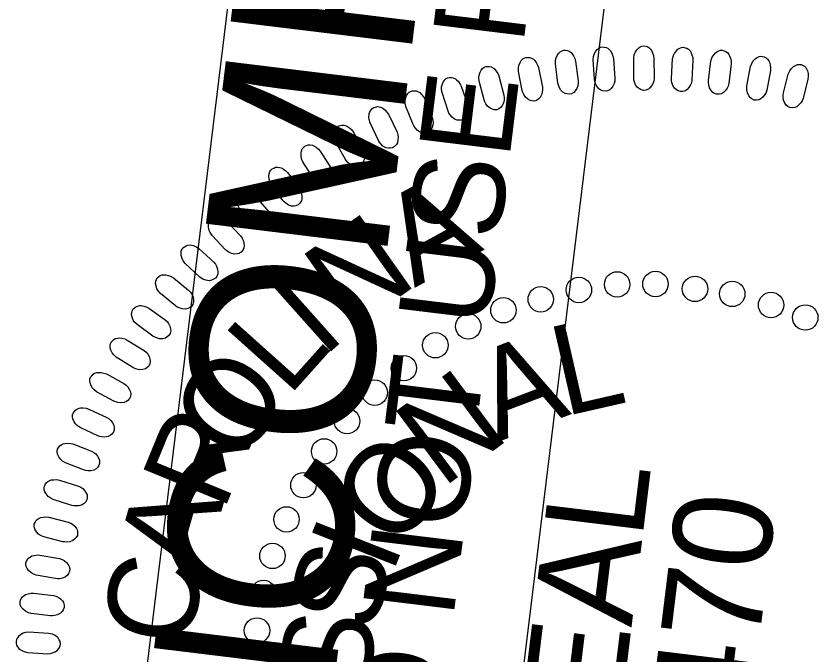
# Model space of a CAD drawing. Extents: x 480344 to 482186, y 489602 to 491961.
# Drawn here: x 481070.6 to 481121.1, y 491781.5 to 491821.7 of the extents above; entities that cross this region are included whole.
import ezdxf

# ---------------------------------------------------------------- set-up
doc = ezdxf.new("R2010")
doc.units = 0
doc.layers.add('Sheet PE Seal Cell', color=7, linetype='Continuous')
doc.layers.add('Sheet Sticker Incomplete CELL', color=7, linetype='Continuous')

msp = doc.modelspace()

# ---------------------------------------------------------------- linework, layer by layer
at = {"layer": 'Sheet PE Seal Cell'}
for points in [[(481109.499, 491817.8), (481109.495, 491819.027), (481109.531, 491819.246), (481109.582, 491819.387), (481109.694, 491819.557), (481109.79, 491819.667), (481109.902, 491819.747), (481110.007, 491819.787), (481110.119, 491819.807), (481110.231, 491819.788), (481110.351, 491819.758), (481110.456, 491819.699), (481110.561, 491819.6), (481110.62, 491819.52), (481110.689, 491819.371), (481110.749, 491819.191), (481110.773, 491819.032), (481110.785, 491817.775), (481110.762, 491817.606), (481110.718, 491817.466), (481110.629, 491817.306), (481110.518, 491817.166), (481110.421, 491817.086), (481110.264, 491817.025), (481110.114, 491817.005), (481109.965, 491817.044), (481109.86, 491817.094), (481109.733, 491817.193), (481109.612, 491817.362), (481109.545, 491817.541), (481109.514, 491817.671)], [(481104.73, 491817.468), (481104.572, 491818.685), (481104.58, 491818.906), (481104.614, 491819.052), (481104.703, 491819.235), (481104.785, 491819.357), (481104.886, 491819.45), (481104.985, 491819.503), (481105.094, 491819.537), (481105.207, 491819.532), (481105.33, 491819.517), (481105.441, 491819.472), (481105.558, 491819.387), (481105.628, 491819.315), (481105.713, 491819.175), (481105.796, 491819.005), (481105.839, 491818.85), (481106.008, 491817.605), (481106.008, 491817.434), (481105.982, 491817.289), (481105.913, 491817.12), (481105.821, 491816.967), (481105.734, 491816.875), (481105.586, 491816.795), (481105.441, 491816.756), (481105.287, 491816.777), (481105.177, 491816.813), (481105.038, 491816.895), (481104.898, 491817.047), (481104.808, 491817.217), (481104.762, 491817.342)], [(481107.029, 491817.701), (481106.948, 491818.925), (481106.971, 491819.146), (481107.013, 491819.289), (481107.114, 491819.466), (481107.203, 491819.581), (481107.31, 491819.669), (481107.411, 491819.715), (481107.522, 491819.743), (481107.635, 491819.73), (481107.757, 491819.708), (481107.865, 491819.656), (481107.976, 491819.563), (481108.041, 491819.488), (481108.118, 491819.343), (481108.19, 491819.168), (481108.223, 491819.01), (481108.314, 491817.756), (481108.303, 491817.586), (481108.267, 491817.444), (481108.188, 491817.279), (481108.086, 491817.132), (481107.995, 491817.046), (481107.841, 491816.975), (481107.693, 491816.946), (481107.542, 491816.976), (481107.434, 491817.018), (481107.301, 491817.109), (481107.171, 491817.271), (481107.091, 491817.446), (481107.053, 491817.573)], [(481111.875, 491817.756), (481111.948, 491818.98), (481111.999, 491819.196), (481112.058, 491819.333), (481112.181, 491819.496), (481112.284, 491819.599), (481112.401, 491819.672), (481112.507, 491819.706), (481112.621, 491819.719), (481112.731, 491819.693), (481112.849, 491819.656), (481112.95, 491819.59), (481113.049, 491819.484), (481113.103, 491819.401), (481113.162, 491819.248), (481113.211, 491819.065), (481113.224, 491818.905), (481113.157, 491817.649), (481113.125, 491817.482), (481113.071, 491817.345), (481112.973, 491817.191), (481112.853, 491817.058), (481112.751, 491816.984), (481112.591, 491816.934), (481112.44, 491816.923), (481112.294, 491816.971), (481112.192, 491817.028), (481112.071, 491817.135), (481111.962, 491817.31), (481111.905, 491817.494), (481111.883, 491817.625)], [(481114.207, 491817.621), (481114.356, 491818.839), (481114.42, 491819.052), (481114.489, 491819.184), (481114.621, 491819.339), (481114.73, 491819.436), (481114.851, 491819.501), (481114.96, 491819.528), (481115.074, 491819.534), (481115.183, 491819.501), (481115.298, 491819.457), (481115.394, 491819.385), (481115.486, 491819.273), (481115.536, 491819.186), (481115.584, 491819.029), (481115.622, 491818.844), (481115.625, 491818.684), (481115.48, 491817.435), (481115.437, 491817.27), (481115.374, 491817.136), (481115.266, 491816.989), (481115.139, 491816.864), (481115.032, 491816.796), (481114.869, 491816.756), (481114.718, 491816.755), (481114.575, 491816.813), (481114.477, 491816.875), (481114.363, 491816.989), (481114.265, 491817.172), (481114.22, 491817.358), (481114.206, 491817.491)], [(481102.482, 491816.992), (481102.248, 491818.197), (481102.243, 491818.419), (481102.267, 491818.567), (481102.345, 491818.754), (481102.419, 491818.881), (481102.514, 491818.98), (481102.609, 491819.039), (481102.716, 491819.08), (481102.829, 491819.082), (481102.953, 491819.076), (481103.066, 491819.037), (481103.189, 491818.959), (481103.263, 491818.892), (481103.358, 491818.758), (481103.45, 491818.594), (481103.503, 491818.441), (481103.751, 491817.209), (481103.76, 491817.039), (481103.743, 491816.893), (481103.686, 491816.719), (481103.603, 491816.561), (481103.522, 491816.463), (481103.38, 491816.374), (481103.237, 491816.327), (481103.082, 491816.337), (481102.97, 491816.366), (481102.826, 491816.44), (481102.677, 491816.583), (481102.576, 491816.747), (481102.522, 491816.868)], [(481116.626, 491817.292), (481116.85, 491818.498), (481116.928, 491818.706), (481117.004, 491818.834), (481117.146, 491818.981), (481117.262, 491819.071), (481117.386, 491819.128), (481117.496, 491819.148), (481117.611, 491819.147), (481117.717, 491819.107), (481117.829, 491819.056), (481117.921, 491818.978), (481118.005, 491818.861), (481118.05, 491818.771), (481118.088, 491818.611), (481118.114, 491818.424), (481118.107, 491818.263), (481117.884, 491817.027), (481117.83, 491816.864), (481117.76, 491816.735), (481117.643, 491816.595), (481117.507, 491816.479), (481117.397, 491816.417), (481117.232, 491816.387), (481117.081, 491816.396), (481116.942, 491816.462), (481116.848, 491816.53), (481116.741, 491816.652), (481116.655, 491816.84), (481116.622, 491817.03), (481116.616, 491817.162)], [(481100.079, 491816.405), (481099.77, 491817.593), (481099.751, 491817.814), (481099.766, 491817.962), (481099.831, 491818.155), (481099.898, 491818.285), (481099.986, 491818.391), (481100.078, 491818.456), (481100.181, 491818.504), (481100.295, 491818.512), (481100.418, 491818.514), (481100.534, 491818.482), (481100.661, 491818.412), (481100.739, 491818.35), (481100.842, 491818.222), (481100.945, 491818.064), (481101.006, 491817.915), (481101.331, 491816.701), (481101.352, 491816.531), (481101.344, 491816.385), (481101.297, 491816.208), (481101.224, 491816.045), (481101.15, 491815.942), (481101.013, 491815.845), (481100.873, 491815.788), (481100.719, 491815.789), (481100.605, 491815.811), (481100.457, 491815.875), (481100.299, 491816.009), (481100.188, 491816.166), (481100.127, 491816.284)], [(481118.928, 491816.843), (481119.228, 491818.033), (481119.318, 491818.236), (481119.403, 491818.359), (481119.553, 491818.497), (481119.675, 491818.579), (481119.803, 491818.628), (481119.914, 491818.641), (481120.028, 491818.633), (481120.131, 491818.586), (481120.24, 491818.528), (481120.327, 491818.444), (481120.404, 491818.322), (481120.442, 491818.23), (481120.471, 491818.068), (481120.485, 491817.88), (481120.467, 491817.72), (481120.167, 491816.499), (481120.104, 491816.34), (481120.026, 491816.216), (481119.9, 491816.084), (481119.757, 491815.976), (481119.643, 491815.922), (481119.476, 491815.903), (481119.327, 491815.92), (481119.191, 491815.995), (481119.102, 491816.069), (481119.003, 491816.197), (481118.929, 491816.39), (481118.907, 491816.581), (481118.911, 491816.714)], [(481097.815, 491815.695), (481097.432, 491816.86), (481097.399, 491817.08), (481097.404, 491817.229), (481097.458, 491817.426), (481097.517, 491817.56), (481097.598, 491817.671), (481097.685, 491817.742), (481097.785, 491817.796), (481097.898, 491817.812), (481098.021, 491817.82), (481098.139, 491817.797), (481098.27, 491817.734), (481098.351, 491817.678), (481098.462, 491817.556), (481098.575, 491817.404), (481098.646, 491817.26), (481099.046, 491816.068), (481099.077, 491815.901), (481099.079, 491815.754), (481099.043, 491815.575), (481098.98, 491815.407), (481098.913, 491815.3), (481098.782, 491815.194), (481098.647, 491815.129), (481098.493, 491815.12), (481098.377, 491815.135), (481098.225, 491815.189), (481098.059, 491815.314), (481097.939, 491815.463), (481097.87, 491815.577)], [(481095.614, 491814.848), (481095.158, 491815.987), (481095.111, 491816.205), (481095.107, 491816.354), (481095.148, 491816.553), (481095.198, 491816.691), (481095.273, 491816.807), (481095.355, 491816.882), (481095.451, 491816.943), (481095.563, 491816.966), (481095.685, 491816.982), (481095.804, 491816.966), (481095.939, 491816.913), (481096.024, 491816.861), (481096.142, 491816.747), (481096.264, 491816.602), (481096.344, 491816.462), (481096.818, 491815.299), (481096.86, 491815.133), (481096.87, 491814.986), (481096.846, 491814.805), (481096.794, 491814.634), (481096.734, 491814.523), (481096.61, 491814.41), (481096.479, 491814.336), (481096.326, 491814.317), (481096.21, 491814.324), (481096.054, 491814.37), (481095.881, 491814.483), (481095.751, 491814.625), (481095.675, 491814.734)], [(481093.426, 491813.845), (481092.899, 491814.953), (481092.839, 491815.168), (481092.826, 491815.316), (481092.854, 491815.517), (481092.895, 491815.658), (481092.962, 491815.778), (481093.04, 491815.859), (481093.132, 491815.925), (481093.242, 491815.956), (481093.363, 491815.98), (481093.483, 491815.971), (481093.621, 491815.925), (481093.709, 491815.879), (481093.834, 491815.772), (481093.965, 491815.636), (481094.054, 491815.502), (481094.6, 491814.371), (481094.652, 491814.208), (481094.671, 491814.062), (481094.659, 491813.88), (481094.618, 491813.705), (481094.564, 491813.591), (481094.448, 491813.47), (481094.322, 491813.388), (481094.17, 491813.36), (481094.054, 491813.36), (481093.896, 491813.395), (481093.715, 491813.497), (481093.577, 491813.631), (481093.495, 491813.735)], [(481091.324, 491812.691), (481090.73, 491813.764), (481090.656, 491813.974), (481090.633, 491814.121), (481090.649, 491814.324), (481090.681, 491814.467), (481090.74, 491814.591), (481090.813, 491814.677), (481090.901, 491814.749), (481091.009, 491814.786), (481091.128, 491814.817), (481091.248, 491814.816), (481091.388, 491814.779), (481091.479, 491814.739), (481091.611, 491814.64), (481091.75, 491814.512), (481091.847, 491814.384), (481092.463, 491813.289), (481092.525, 491813.13), (481092.554, 491812.985), (481092.553, 491812.803), (481092.523, 491812.626), (481092.477, 491812.509), (481092.368, 491812.381), (481092.247, 491812.29), (481092.097, 491812.253), (481091.982, 491812.246), (481091.822, 491812.271), (481091.635, 491812.362), (481091.489, 491812.486), (481091.4, 491812.585)], [(481089.338, 491811.462), (481088.677, 491812.496), (481088.59, 491812.701), (481088.559, 491812.847), (481088.562, 491813.05), (481088.585, 491813.195), (481088.636, 491813.322), (481088.703, 491813.412), (481088.787, 491813.49), (481088.892, 491813.533), (481089.009, 491813.572), (481089.129, 491813.579), (481089.271, 491813.551), (481089.365, 491813.516), (481089.502, 491813.426), (481089.648, 491813.307), (481089.754, 491813.185), (481090.437, 491812.13), (481090.51, 491811.976), (481090.547, 491811.834), (481090.557, 491811.651), (481090.539, 491811.473), (481090.5, 491811.353), (481090.4, 491811.218), (481090.284, 491811.121), (481090.137, 491811.074), (481090.022, 491811.059), (481089.861, 491811.075), (481089.669, 491811.153), (481089.516, 491811.268), (481089.421, 491811.361)], [(481087.409, 491810.074), (481086.685, 491811.064), (481086.586, 491811.263), (481086.545, 491811.407), (481086.535, 491811.609), (481086.549, 491811.755), (481086.592, 491811.886), (481086.653, 491811.98), (481086.731, 491812.063), (481086.834, 491812.112), (481086.948, 491812.159), (481087.068, 491812.173), (481087.211, 491812.154), (481087.306, 491812.125), (481087.449, 491812.044), (481087.603, 491811.935), (481087.716, 491811.819), (481088.464, 491810.809), (481088.546, 491810.66), (481088.593, 491810.52), (481088.614, 491810.339), (481088.607, 491810.16), (481088.575, 491810.038), (481088.484, 491809.897), (481088.375, 491809.792), (481088.231, 491809.736), (481088.117, 491809.715), (481087.956, 491809.72), (481087.759, 491809.786), (481087.599, 491809.892), (481087.498, 491809.979)], [(481085.517, 491808.548), (481084.732, 491809.49), (481084.619, 491809.682), (481084.57, 491809.823), (481084.548, 491810.025), (481084.552, 491810.172), (481084.587, 491810.305), (481084.642, 491810.403), (481084.716, 491810.49), (481084.814, 491810.546), (481084.925, 491810.6), (481085.044, 491810.621), (481085.188, 491810.611), (481085.286, 491810.588), (481085.433, 491810.516), (481085.594, 491810.417), (481085.713, 491810.309), (481086.523, 491809.348), (481086.615, 491809.204), (481086.67, 491809.068), (481086.703, 491808.888), (481086.707, 491808.709), (481086.683, 491808.585), (481086.601, 491808.438), (481086.498, 491808.327), (481086.358, 491808.263), (481086.246, 491808.234), (481086.085, 491808.229), (481085.884, 491808.283), (481085.718, 491808.377), (481085.612, 491808.458)], [(481083.8, 491806.973), (481082.956, 491807.864), (481082.833, 491808.049), (481082.775, 491808.186), (481082.739, 491808.387), (481082.734, 491808.533), (481082.761, 491808.668), (481082.81, 491808.769), (481082.878, 491808.861), (481082.972, 491808.923), (481083.08, 491808.983), (481083.197, 491809.012), (481083.342, 491809.011), (481083.44, 491808.995), (481083.592, 491808.932), (481083.759, 491808.843), (481083.885, 491808.743), (481084.754, 491807.835), (481084.854, 491807.696), (481084.917, 491807.564), (481084.962, 491807.387), (481084.977, 491807.208), (481084.961, 491807.083), (481084.888, 491806.932), (481084.793, 491806.815), (481084.657, 491806.741), (481084.547, 491806.705), (481084.386, 491806.69), (481084.183, 491806.731), (481084.01, 491806.816), (481083.899, 491806.889)], [(481082.164, 491805.264), (481081.267, 491806.1), (481081.131, 491806.277), (481081.065, 491806.411), (481081.017, 491806.608), (481081.003, 491806.754), (481081.021, 491806.89), (481081.064, 491806.995), (481081.125, 491807.09), (481081.216, 491807.159), (481081.32, 491807.225), (481081.435, 491807.261), (481081.579, 491807.27), (481081.679, 491807.26), (481081.834, 491807.207), (481082.006, 491807.128), (481082.138, 491807.036), (481083.062, 491806.184), (481083.171, 491806.052), (481083.242, 491805.924), (481083.298, 491805.75), (481083.324, 491805.573), (481083.316, 491805.447), (481083.253, 491805.291), (481083.165, 491805.169), (481083.034, 491805.086), (481082.926, 491805.044), (481082.767, 491805.019), (481082.561, 491805.047), (481082.384, 491805.12), (481082.269, 491805.187)], [(481080.658, 491803.434), (481079.71, 491804.212), (481079.564, 491804.38), (481079.489, 491804.509), (481079.429, 491804.703), (481079.405, 491804.848), (481079.415, 491804.985), (481079.451, 491805.091), (481079.507, 491805.191), (481079.593, 491805.265), (481079.692, 491805.337), (481079.805, 491805.381), (481079.948, 491805.399), (481080.048, 491805.394), (481080.207, 491805.351), (481080.383, 491805.284), (481080.521, 491805.2), (481081.497, 491804.408), (481081.613, 491804.283), (481081.693, 491804.16), (481081.759, 491803.989), (481081.796, 491803.814), (481081.797, 491803.688), (481081.743, 491803.529), (481081.663, 491803.401), (481081.538, 491803.311), (481081.432, 491803.262), (481081.275, 491803.226), (481081.068, 491803.242), (481080.887, 491803.303), (481080.767, 491803.363)], [(481079.232, 491801.534), (481078.237, 491802.251), (481078.081, 491802.41), (481077.998, 491802.534), (481077.926, 491802.724), (481077.894, 491802.867), (481077.895, 491803.005), (481077.923, 491803.113), (481077.973, 491803.216), (481078.055, 491803.295), (481078.149, 491803.374), (481078.258, 491803.424), (481078.401, 491803.451), (481078.5, 491803.453), (481078.661, 491803.42), (481078.842, 491803.363), (481078.984, 491803.289), (481080.008, 491802.56), (481080.132, 491802.442), (481080.22, 491802.324), (481080.297, 491802.159), (481080.344, 491801.985), (481080.352, 491801.86), (481080.309, 491801.698), (481080.238, 491801.565), (481080.118, 491801.466), (481080.016, 491801.411), (481079.861, 491801.366), (481079.653, 491801.368), (481079.469, 491801.419), (481079.345, 491801.47)], [(481077.967, 491799.549), (481076.928, 491800.202), (481076.763, 491800.351), (481076.672, 491800.469), (481076.588, 491800.655), (481076.547, 491800.795), (481076.54, 491800.933), (481076.562, 491801.042), (481076.605, 491801.148), (481076.681, 491801.232), (481076.77, 491801.318), (481076.876, 491801.374), (481077.017, 491801.41), (481077.116, 491801.418), (481077.279, 491801.395), (481077.462, 491801.35), (481077.61, 491801.284), (481078.677, 491800.621), (481078.808, 491800.512), (481078.903, 491800.399), (481078.99, 491800.238), (481079.048, 491800.069), (481079.064, 491799.944), (481079.031, 491799.779), (481078.968, 491799.642), (481078.855, 491799.538), (481078.757, 491799.476), (481078.605, 491799.421), (481078.398, 491799.41), (481078.21, 491799.449), (481078.085, 491799.493)], [(481076.768, 491797.437), (481075.691, 491798.024), (481075.516, 491798.162), (481075.418, 491798.274), (481075.323, 491798.454), (481075.273, 491798.592), (481075.257, 491798.729), (481075.272, 491798.84), (481075.307, 491798.948), (481075.379, 491799.036), (481075.462, 491799.127), (481075.565, 491799.19), (481075.703, 491799.235), (481075.801, 491799.249), (481075.965, 491799.237), (481076.151, 491799.204), (481076.302, 491799.147), (481077.409, 491798.552), (481077.547, 491798.451), (481077.648, 491798.345), (481077.745, 491798.19), (481077.815, 491798.025), (481077.838, 491797.901), (481077.815, 491797.735), (481077.761, 491797.594), (481077.655, 491797.482), (481077.561, 491797.414), (481077.413, 491797.35), (481077.206, 491797.326), (481077.017, 491797.352), (481076.889, 491797.389)], [(481075.761, 491795.26), (481074.649, 491795.778), (481074.466, 491795.905), (481074.362, 491796.011), (481074.255, 491796.184), (481074.197, 491796.319), (481074.172, 491796.454), (481074.18, 491796.566), (481074.209, 491796.676), (481074.275, 491796.769), (481074.353, 491796.865), (481074.451, 491796.935), (481074.585, 491796.987), (481074.683, 491797.007), (481074.847, 491797.006), (481075.035, 491796.984), (481075.189, 491796.937), (481076.331, 491796.413), (481076.476, 491796.321), (481076.583, 491796.221), (481076.691, 491796.073), (481076.769, 491795.912), (481076.801, 491795.79), (481076.789, 491795.622), (481076.743, 491795.478), (481076.644, 491795.36), (481076.555, 491795.286), (481076.411, 491795.213), (481076.207, 491795.176), (481076.015, 491795.191), (481075.885, 491795.219)], [(481074.871, 491793.102), (481073.729, 491793.549), (481073.539, 491793.664), (481073.427, 491793.764), (481073.31, 491793.93), (481073.243, 491794.06), (481073.21, 491794.194), (481073.211, 491794.306), (481073.233, 491794.418), (481073.293, 491794.515), (481073.364, 491794.615), (481073.458, 491794.691), (481073.589, 491794.752), (481073.685, 491794.778), (481073.849, 491794.786), (481074.038, 491794.777), (481074.195, 491794.74), (481075.368, 491794.288), (481075.517, 491794.205), (481075.631, 491794.112), (481075.747, 491793.971), (481075.836, 491793.816), (481075.875, 491793.696), (481075.873, 491793.528), (481075.837, 491793.382), (481075.745, 491793.257), (481075.661, 491793.178), (481075.522, 491793.096), (481075.32, 491793.046), (481075.129, 491793.049), (481074.998, 491793.069)], [(481074.121, 491790.871), (481072.953, 491791.246), (481072.756, 491791.348), (481072.639, 491791.441), (481072.512, 491791.6), (481072.437, 491791.725), (481072.395, 491791.856), (481072.389, 491791.968), (481072.404, 491792.082), (481072.457, 491792.182), (481072.523, 491792.287), (481072.612, 491792.368), (481072.739, 491792.437), (481072.832, 491792.47), (481072.996, 491792.488), (481073.185, 491792.491), (481073.344, 491792.463), (481074.543, 491792.086), (481074.697, 491792.013), (481074.816, 491791.928), (481074.941, 491791.794), (481075.04, 491791.644), (481075.086, 491791.527), (481075.095, 491791.36), (481075.068, 491791.211), (481074.985, 491791.081), (481074.905, 491790.997), (481074.772, 491790.906), (481074.574, 491790.844), (481074.382, 491790.835), (481074.249, 491790.846)], [(481073.553, 491788.584), (481072.364, 491788.885), (481072.16, 491788.974), (481072.038, 491789.059), (481071.901, 491789.209), (481071.818, 491789.331), (481071.769, 491789.459), (481071.755, 491789.57), (481071.764, 491789.684), (481071.811, 491789.788), (481071.869, 491789.896), (481071.953, 491789.983), (481072.075, 491790.06), (481072.167, 491790.098), (481072.329, 491790.127), (481072.517, 491790.141), (481072.677, 491790.124), (481073.898, 491789.823), (481074.056, 491789.759), (481074.18, 491789.682), (481074.313, 491789.556), (481074.421, 491789.413), (481074.475, 491789.3), (481074.494, 491789.132), (481074.477, 491788.983), (481074.402, 491788.847), (481074.328, 491788.758), (481074.2, 491788.659), (481074.006, 491788.585), (481073.816, 491788.564), (481073.682, 491788.567)], [(481073.093, 491786.26), (481071.887, 491786.485), (481071.678, 491786.562), (481071.551, 491786.639), (481071.405, 491786.781), (481071.315, 491786.896), (481071.257, 491787.021), (481071.237, 491787.132), (481071.238, 491787.246), (481071.279, 491787.352), (481071.33, 491787.464), (481071.408, 491787.556), (481071.525, 491787.641), (481071.614, 491787.684), (481071.774, 491787.724), (481071.961, 491787.749), (481072.122, 491787.742), (481073.359, 491787.518), (481073.521, 491787.465), (481073.65, 491787.395), (481073.79, 491787.278), (481073.907, 491787.142), (481073.968, 491787.032), (481073.998, 491786.867), (481073.99, 491786.716), (481073.924, 491786.576), (481073.855, 491786.483), (481073.733, 491786.376), (481073.545, 491786.29), (481073.356, 491786.256), (481073.223, 491786.251)], [(481072.781, 491783.921), (481071.563, 491784.07), (481071.35, 491784.134), (481071.217, 491784.204), (481071.063, 491784.335), (481070.966, 491784.445), (481070.9, 491784.566), (481070.874, 491784.675), (481070.867, 491784.789), (481070.901, 491784.897), (481070.945, 491785.013), (481071.017, 491785.109), (481071.129, 491785.201), (481071.216, 491785.25), (481071.372, 491785.299), (481071.558, 491785.337), (481071.719, 491785.34), (481072.967, 491785.194), (481073.132, 491785.152), (481073.265, 491785.09), (481073.413, 491784.981), (481073.538, 491784.853), (481073.605, 491784.747), (481073.645, 491784.583), (481073.647, 491784.433), (481073.59, 491784.29), (481073.527, 491784.192), (481073.413, 491784.077), (481073.23, 491783.979), (481073.044, 491783.934), (481072.911, 491783.921)], [(481072.655, 491782.813), (481071.43, 491782.886), (481071.209, 491782.861), (481071.067, 491782.817), (481070.89, 491782.715), (481070.775, 491782.625), (481070.689, 491782.518), (481070.643, 491782.416), (481070.617, 491782.304), (481070.63, 491782.192), (481070.652, 491782.071), (481070.706, 491781.962), (481070.8, 491781.852), (481070.876, 491781.788), (481071.021, 491781.712), (481071.197, 491781.641), (481071.354, 491781.61), (481072.609, 491781.528), (481072.779, 491781.54), (481072.921, 491781.577), (481073.086, 491781.657), (481073.232, 491781.761), (481073.317, 491781.853), (481073.386, 491782.007), (481073.415, 491782.154), (481073.384, 491782.306), (481073.34, 491782.414), (481073.248, 491782.546), (481073.086, 491782.676), (481072.91, 491782.753), (481072.783, 491782.791)]]:
    msp.add_lwpolyline(points, close=True, dxfattribs=at)
for centre in [(481106.045, 491804.437), (481108.455, 491804.784), (481110.866, 491804.81), (481113.357, 491804.504), (481103.645, 491803.849), (481115.7, 491804.188), (481118.143, 491803.488), (481101.294, 491803.157), (481120.294, 491802.703), (481099.083, 491802.144), (481097.011, 491800.954), (481095.028, 491799.512), (481093.194, 491797.971), (481091.45, 491796.18), (481090.012, 491794.27), (481088.708, 491792.143), (481087.641, 491789.988), (481086.757, 491787.689), (481086.19, 491785.352), (481085.781, 491782.995)]:
    msp.add_circle(centre, 0.801, dxfattribs=at)
at = {"layer": 'Sheet Sticker Incomplete CELL'}
msp.add_lwpolyline([(481099.711, 491757.426), (481076.384, 491760.275), (481094.206, 491906.191), (481117.533, 491903.342)], close=True, dxfattribs=at)

# ---------------------------------------------------------------- texts
at = {"layer": 'Sheet PE Seal Cell'}
for s, height, rotation, p in [('A', 5.669, 28.7093, (481095.698, 491804.558)), ('N', 5.669, 35.1987, (481091.544, 491801.721)), ('I', 5.669, 41.688, (481089.915, 491800.101)), ('L', 5.669, 48.1774, (481087.749, 491797.653)), ('L', 5.669, 12.8674, (481105.12, 491796.464)), ('A', 5.669, 20.8072, (481100.898, 491794.84)), ('O', 5.669, 54.6668, (481084.663, 491793.261)), ('N', 5.669, 36.6868, (481097.435, 491791.901)), ('R', 5.669, 67.6455, (481083.655, 491790.408)), ('O', 5.669, 52.5664, (481094.625, 491787.901)), ('SEAL', 6.2363, 83.0179, (481108.001, 491772.114)), ('A', 5.669, 74.1348, (481082.357, 491786.328)), ('29470', 6.2363, 83.0179, (481115.66, 491768.185)), ('I', 5.669, 68.4459, (481094.272, 491786.429)), ('S', 5.669, 76.3857, (481093.184, 491782.733)), ('C', 5.669, 80.6242, (481081.596, 491781.812)), ('S', 5.669, 84.3255, (481092.817, 491778.889))]:
    msp.add_text(s, height=height, rotation=rotation, dxfattribs=at).set_placement(p)
at = {"layer": 'Sheet Sticker Incomplete CELL'}
for s, height, p in [('INCOMPLETE PLANS', 11.52, (481089.182, 491767.729)), ('DO NOT USE FOR R/W ACQUISITION', 5.76, (481096.475, 491770.112))]:
    msp.add_text(s, height=height, rotation=83.0365, dxfattribs=at).set_placement(p)

doc.saveas('drawing.dxf')
